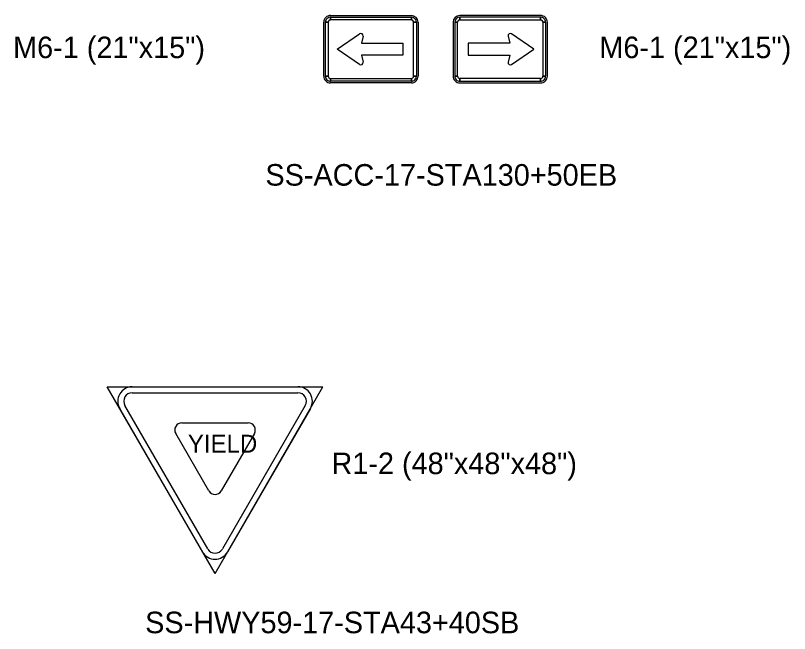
# Model space of a CAD drawing. Extents: x 620856.8 to 620948.6, y 415598.8 to 415658.2.
# Drawn here: x 620857.63 to 620871.99, y 415631.42 to 415642.88 of the extents above; entities that cross this region are included whole.
import ezdxf

# ---------------------------------------------------------------- set-up
doc = ezdxf.new("R2010")
doc.units = 0
doc.layers.add('SIGNS', color=7, linetype='Continuous')

msp = doc.modelspace()

# ---------------------------------------------------------------- linework, layer by layer
at = {"layer": 'SIGNS'}
for p, q in [((620863.479, 415642.884), (620864.979, 415642.884)), ((620863.479, 415642.853), (620863.479, 415642.801)), ((620864.979, 415642.801), (620864.979, 415642.853)), ((620867.377, 415642.884), (620865.877, 415642.884)), ((620865.877, 415642.801), (620865.877, 415642.853)), ((620867.377, 415642.853), (620867.377, 415642.801)), ((620863.354, 415641.759), (620863.354, 415642.759)), ((620863.437, 415642.759), (620863.385, 415642.759)), ((620865.073, 415642.759), (620865.021, 415642.759)), ((620865.104, 415642.759), (620865.104, 415641.759)), ((620865.752, 415642.759), (620865.752, 415641.759)), ((620865.783, 415642.759), (620865.835, 415642.759)), ((620867.419, 415642.759), (620867.471, 415642.759)), ((620867.502, 415641.759), (620867.502, 415642.759)), ((620863.604, 415642.259), (620864.019, 415642.545)), ((620867.252, 415642.259), (620866.837, 415642.545)), ((620864.082, 415642.5), (620864.052, 415642.369)), ((620866.774, 415642.5), (620866.804, 415642.369)), ((620863.604, 415642.259), (620863.604, 415642.259)), ((620864.019, 415641.974), (620863.604, 415642.259)), ((620864.052, 415642.369), (620864.823, 415642.369)), ((620864.823, 415642.369), (620864.823, 415642.15)), ((620866.804, 415642.369), (620866.033, 415642.369)), ((620866.033, 415642.369), (620866.033, 415642.15)), ((620866.837, 415641.974), (620867.252, 415642.259)), ((620867.252, 415642.259), (620867.252, 415642.259)), ((620864.823, 415642.15), (620864.052, 415642.15)), ((620864.052, 415642.15), (620864.082, 415642.019)), ((620864.823, 415642.15), (620864.823, 415642.15)), ((620866.033, 415642.15), (620866.033, 415642.15)), ((620866.033, 415642.15), (620866.804, 415642.15)), ((620866.804, 415642.15), (620866.774, 415642.019)), ((620863.385, 415641.759), (620863.437, 415641.759)), ((620863.479, 415641.718), (620863.479, 415641.666)), ((620864.979, 415641.666), (620864.979, 415641.718)), ((620865.021, 415641.759), (620865.073, 415641.759)), ((620865.835, 415641.759), (620865.783, 415641.759)), ((620865.877, 415641.666), (620865.877, 415641.718)), ((620867.377, 415641.718), (620867.377, 415641.666)), ((620867.471, 415641.759), (620867.419, 415641.759)), ((620864.979, 415641.634), (620863.479, 415641.634)), ((620865.877, 415641.634), (620867.377, 415641.634)), ((620859.337, 415635.997), (620863.337, 415635.997)), ((620861.337, 415632.533), (620859.337, 415635.997)), ((620859.799, 415635.997), (620862.875, 415635.997)), ((620861.337, 415632.533), (620863.337, 415635.997)), ((620859.799, 415635.886), (620862.875, 415635.886)), ((620861.202, 415632.989), (620859.664, 415635.653)), ((620863.01, 415635.653), (620861.472, 415632.989)), ((620861.106, 415632.933), (620859.568, 415635.597)), ((620863.106, 415635.597), (620861.568, 415632.933)), ((620860.722, 415635.33), (620861.951, 415635.33)), ((620861.221, 415634.066), (620860.607, 415635.13)), ((620862.067, 415635.13), (620861.452, 415634.066))]:
    msp.add_line(p, q, dxfattribs=at)
for points in [[(620863.479, 415642.853), (620864.979, 415642.853), (620864.979, 415642.801), (620863.479, 415642.801), (620863.479, 415642.853), (620863.479, 415642.853)], [(620867.377, 415642.853), (620865.877, 415642.853), (620865.877, 415642.801), (620867.377, 415642.801), (620867.377, 415642.853), (620867.377, 415642.853)], [(620863.385, 415641.759), (620863.385, 415642.759), (620863.437, 415642.759), (620863.437, 415641.759), (620863.385, 415641.759), (620863.385, 415641.759)], [(620865.073, 415642.759), (620865.073, 415641.759), (620865.021, 415641.759), (620865.021, 415642.759), (620865.073, 415642.759), (620865.073, 415642.759)], [(620865.783, 415642.759), (620865.783, 415641.759), (620865.835, 415641.759), (620865.835, 415642.759), (620865.783, 415642.759), (620865.783, 415642.759)], [(620867.471, 415641.759), (620867.471, 415642.759), (620867.419, 415642.759), (620867.419, 415641.759), (620867.471, 415641.759), (620867.471, 415641.759)], [(620864.979, 415641.666), (620863.479, 415641.666), (620863.479, 415641.718), (620864.979, 415641.718), (620864.979, 415641.666), (620864.979, 415641.666)], [(620865.877, 415641.666), (620867.377, 415641.666), (620867.377, 415641.718), (620865.877, 415641.718), (620865.877, 415641.666), (620865.877, 415641.666)]]:
    msp.add_lwpolyline(points, close=True, dxfattribs=at)
for centre, radius, start, end in [((620863.479, 415642.759), 0.125, 89.9998, 180), ((620863.479, 415642.759), 0.0937, 89.9998, 180), ((620864.979, 415642.759), 0.125, 0.0002, 89.9998), ((620864.979, 415642.759), 0.0937, 0.0002, 89.9998), ((620865.877, 415642.759), 0.125, 90.0002, 179.9998), ((620865.877, 415642.759), 0.0937, 90.0002, 179.9998), ((620867.377, 415642.759), 0.125, 360, 90.0002), ((620867.377, 415642.759), 0.0937, 360, 90.0002), ((620863.479, 415642.759), 0.0417, 89.9998, 180), ((620864.979, 415642.759), 0.0417, 0.0002, 89.9998), ((620865.877, 415642.759), 0.0417, 90.0002, 179.9998), ((620867.377, 415642.759), 0.0417, 360, 90.0002), ((620864.042, 415642.509), 0.0417, 347.0496, 122.2756), ((620866.815, 415642.509), 0.0417, 57.7244, 192.9504), ((620864.042, 415642.009), 0.0417, 237.7241, 12.9501), ((620866.815, 415642.009), 0.0417, 167.0499, 302.2759), ((620863.479, 415641.759), 0.125, 179.9997, 269.9999), ((620863.479, 415641.759), 0.0937, 179.9997, 269.9999), ((620863.479, 415641.759), 0.0417, 179.9997, 269.9999), ((620864.979, 415641.759), 0.0937, 269.9999, 0.0002), ((620864.979, 415641.759), 0.0417, 269.9999, 0.0002), ((620864.979, 415641.759), 0.125, 269.9999, 0.0002), ((620865.877, 415641.759), 0.125, 179.9998, 270.0001), ((620865.877, 415641.759), 0.0937, 179.9998, 270.0001), ((620865.877, 415641.759), 0.0417, 179.9998, 270.0001), ((620867.377, 415641.759), 0.0937, 270.0001, 0.0003), ((620867.377, 415641.759), 0.0417, 270.0001, 0.0003), ((620867.377, 415641.759), 0.125, 270.0001, 0.0003), ((620859.799, 415635.73), 0.267, 90, 210), ((620862.875, 415635.73), 0.267, 330, 90), ((620859.799, 415635.73), 0.156, 90, 210), ((620862.875, 415635.73), 0.156, 330, 90), ((620860.722, 415635.197), 0.133, 90, 210), ((620861.951, 415635.197), 0.133, 330, 90), ((620861.337, 415634.133), 0.133, 210, 330), ((620861.337, 415633.066), 0.267, 210, 330), ((620861.337, 415633.066), 0.156, 210, 330)]:
    msp.add_arc(centre, radius, start, end, dxfattribs=at)

# ---------------------------------------------------------------- texts
for s, p in [('M6-1 (21"x15")', (620857.59, 415642.093)), ('M6-1 (21"x15")', (620868.467, 415642.093)), ('SS-ACC-17-STA130+50EB', (620862.271, 415639.728)), ('R1-2 (48"x48"x48")', (620863.497, 415634.377)), ('SS-HWY59-17-STA43+40SB', (620860.04, 415631.426))]:
    msp.add_text(s, height=0.4, rotation=0, dxfattribs=at).set_placement(p)
msp.add_text('YIELD', height=0.3333, dxfattribs=at).set_placement((620860.832, 415634.775))

doc.saveas('drawing.dxf')
